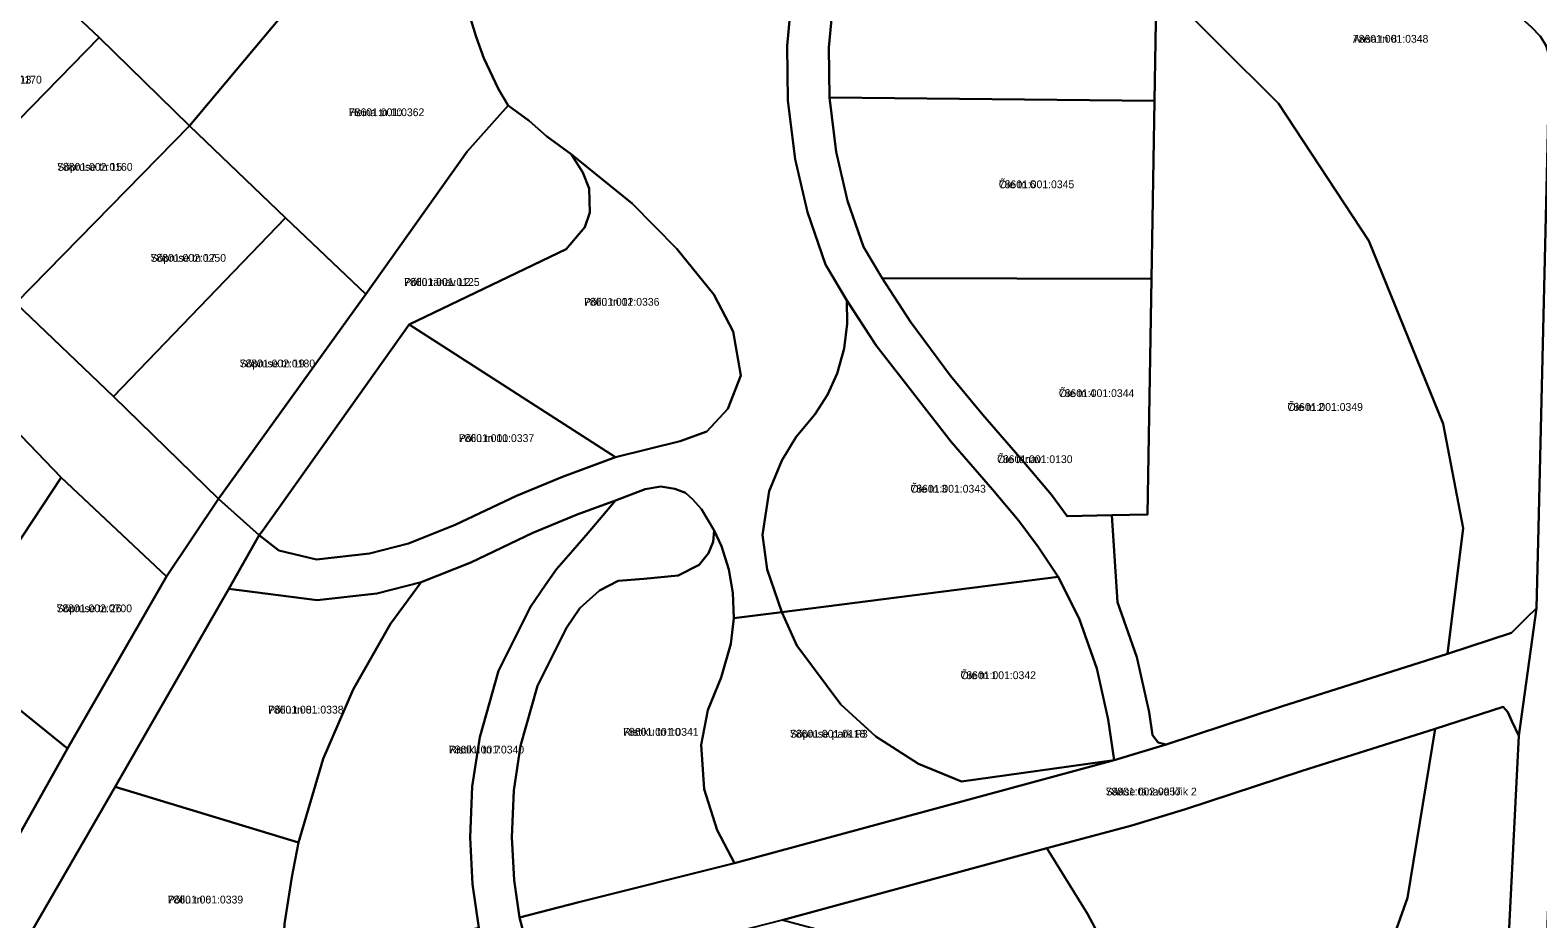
# Model space of a CAD drawing. Extents: x 587616 to 632239, y 6547421 to 6574977.
# Drawn here: x 621332.9 to 621622.8, y 6559852.1 to 6560022.9 of the extents above; entities that cross this region are included whole.
import ezdxf

# ---------------------------------------------------------------- set-up
doc = ezdxf.new("R2010")
doc.units = 0
for name, color, linetype in [('L_AADRESS', 7, 'Continuous'), ('PIIR', 7, 'Continuous'), ('TUNNUS', 7, 'Continuous')]:
    doc.layers.add(name, color=color, linetype=linetype)

msp = doc.modelspace()

# ---------------------------------------------------------------- linework, layer by layer
at = {"layer": 'PIIR'}
for points in [[(621172.9, 6560123.58), (621198.99, 6560110.14), (621218.43, 6560085.97), (621246.55, 6560050.95), (621258.82, 6560038.95), (621276.47, 6560022.13), (621295.15, 6560004.21), (621312.68, 6559987.24), (621330.19, 6559970.43), (621348.95, 6559952.47), (621369.13, 6559932.82), (621359.14, 6559917.91), (621338.93, 6559936.88), (621318.9, 6559957.64), (621298.13, 6559978.99), (621279.17, 6559996.39), (621259.98, 6560016.38), (621241.93, 6560035.63), (621232.97, 6560044.15), (621219.04, 6560061.46), (621203.25, 6560080.3), (621188.53, 6560098.22), (621176.13, 6560115.67)], [(621536.44, 6560099.15), (621540.2, 6560106.23), (621559.61, 6560089.04), (621633.19, 6560023.8), (621630.45, 6559908.6), (621626.31, 6559895.58), (621623.07, 6559813.27), (621623.06, 6559791.54), (621613.88, 6559788.46), (621614.76, 6559790.78), (621615.13, 6559793.22), (621615.42, 6559813.44), (621619.1, 6559887.24), (621622.52, 6559911.82), (621622.89, 6559927.25), (621625.01, 6560016.97), (621624.82, 6560018.4), (621624.34, 6560019.9), (621623.31, 6560021.7), (621621.48, 6560023.54), (621559.14, 6560078.76)], [(621550.22, 6560080.41), (621554.62, 6560079.78), (621556.99, 6560079.25), (621559.14, 6560078.76), (621621.48, 6560023.54), (621623.31, 6560021.7), (621624.34, 6560019.9), (621624.82, 6560018.4), (621625.01, 6560016.97), (621622.89, 6559927.25), (621622.52, 6559911.82), (621620.61, 6559909.96), (621617.69, 6559907.06), (621605.37, 6559902.99), (621608.41, 6559927.16), (621604.55, 6559947.22), (621590.3, 6559982.41), (621572.92, 6560008.78), (621549.43, 6560032.17), (621549.52, 6560037.6)], [(621363.58, 6560004.5), (621346.22, 6560021.46), (621335.3, 6560031.84), (621367.17, 6560067.51), (621388.54, 6560064.01), (621391.19, 6560062.51), (621394.58, 6560059.76), (621396.67, 6560057.03), (621397.89, 6560053.95), (621398.24, 6560050.2), (621398.45, 6560046.35), (621397.05, 6560044.66), (621391.8, 6560038.3)], [(621486.6, 6560009.93), (621486.49, 6560019.59), (621487.35, 6560029.14), (621489.03, 6560037.61), (621491.36, 6560045.61), (621493.83, 6560052.43), (621549.52, 6560037.6), (621549.43, 6560032.17), (621549.06, 6560009.34)], [(621295.15, 6560004.21), (621328.79, 6560038.03), (621335.3, 6560031.84), (621346.22, 6560021.46), (621312.68, 6559987.24)], [(621391.8, 6560038.3), (621416.5, 6560030.15), (621417.65, 6560024.98), (621418.65, 6560021.64), (621420.16, 6560017.54), (621422.98, 6560011.59), (621424.85, 6560008.43), (621416.95, 6559999.58), (621397.47, 6559972.15), (621382, 6559986.81), (621363.58, 6560004.5)], [(621548.5, 6559975.1), (621549.06, 6560009.34), (621549.43, 6560032.17), (621572.92, 6560008.78), (621590.3, 6559982.41), (621604.55, 6559947.22), (621608.41, 6559927.16), (621605.37, 6559902.99), (621573.48, 6559892.9), (621551.32, 6559885.6), (621549.78, 6559885.98), (621548.69, 6559887.36), (621548.02, 6559891.83), (621545.71, 6559902.38), (621541.97, 6559912.96), (621540.87, 6559929.64), (621547.76, 6559929.77)], [(621312.68, 6559987.24), (621346.22, 6560021.46), (621363.58, 6560004.5), (621330.19, 6559970.43)], [(621376.95, 6559925.81), (621369.13, 6559932.82), (621397.47, 6559972.15), (621416.95, 6559999.58), (621424.85, 6560008.43), (621428.89, 6560005.5), (621432.18, 6560002.51), (621436.96, 6559999.07), (621439.21, 6559995.57), (621440.38, 6559992.46), (621440.54, 6559987.87), (621439.58, 6559985.03), (621436.01, 6559980.82), (621405.8, 6559966.31), (621377.69, 6559926.74)], [(621496.71, 6559975.25), (621493.14, 6559981.26), (621490.06, 6559990.12), (621487.89, 6559999.52), (621486.6, 6560009.93), (621549.06, 6560009.34), (621548.5, 6559975.1)], [(621330.19, 6559970.43), (621363.58, 6560004.5), (621382, 6559986.81), (621348.95, 6559952.47)], [(621405.8, 6559966.31), (621436.01, 6559980.82), (621439.58, 6559985.03), (621440.54, 6559987.87), (621440.38, 6559992.46), (621439.21, 6559995.57), (621436.96, 6559999.07), (621448.64, 6559989.58), (621457.24, 6559980.88), (621464.34, 6559972.1), (621468.11, 6559964.97), (621469.57, 6559956.49), (621467.05, 6559950.12), (621463.04, 6559945.75), (621457.9, 6559943.9), (621445.48, 6559940.79)], [(621348.95, 6559952.47), (621382, 6559986.81), (621397.47, 6559972.15), (621369.13, 6559932.82)], [(621532.32, 6559929.49), (621529.27, 6559933.56), (621526.14, 6559937.3), (621524.01, 6559939.81), (621516.1, 6559948.93), (621509.88, 6559956.44), (621502.16, 6559966.83), (621496.71, 6559975.25), (621548.5, 6559975.1), (621547.76, 6559929.77), (621540.87, 6559929.64)], [(621477.43, 6559911.01), (621474.64, 6559919.25), (621473.75, 6559925.86), (621475, 6559934.26), (621477.45, 6559940.21), (621480.17, 6559944.75), (621483.75, 6559949.05), (621486.22, 6559952.83), (621488.07, 6559956.93), (621489.42, 6559961.68), (621490.02, 6559966.47), (621489.91, 6559971.03), (621495.59, 6559962.26), (621509.99, 6559943.76), (621517.93, 6559934.61), (621523.01, 6559928.58), (621526.73, 6559923.61), (621530.58, 6559917.83)], [(621387.96, 6559921.15), (621380.75, 6559922.87), (621376.95, 6559925.81), (621377.69, 6559926.74), (621405.8, 6559966.31), (621445.48, 6559940.79), (621435.27, 6559937.07), (621426.43, 6559933.41), (621414.63, 6559927.83), (621405.68, 6559924.21), (621398.19, 6559922.33)], [(621318.9, 6559957.64), (621338.93, 6559936.88), (621316.89, 6559903.64), (621295.47, 6559922.2)], [(621318.19, 6559902.52), (621316.89, 6559903.64), (621338.93, 6559936.88), (621359.14, 6559917.91), (621340.1, 6559884.83)], [(621259.58, 6559758.94), (621287.55, 6559800.32), (621311.92, 6559839.64), (621319.72, 6559848.57), (621340.1, 6559884.83), (621359.14, 6559917.91), (621369.13, 6559932.82), (621376.95, 6559925.81), (621371.15, 6559915.5), (621349.26, 6559877.47), (621329.06, 6559842.38), (621319.31, 6559827.3), (621309.9, 6559812.66), (621296.45, 6559791.82), (621270.07, 6559749.48)], [(621381.35, 6559840.54), (621381.82, 6559851.12), (621383.22, 6559860.07), (621384.54, 6559866.75), (621389.24, 6559882.8), (621395.01, 6559896.15), (621402.23, 6559908.78), (621408.11, 6559916.77), (621417.64, 6559920.59), (621429.59, 6559926.28), (621438.1, 6559929.8), (621445.45, 6559932.48), (621442.3, 6559928.77), (621440.23, 6559926.29), (621437.26, 6559922.88), (621434.11, 6559919.3), (621431.98, 6559916.3), (621429.12, 6559912.07), (621422.96, 6559899.75), (621419.38, 6559887.02), (621417.92, 6559877.53), (621417.51, 6559867.72), (621418, 6559858.73), (621419.21, 6559850.34)], [(621438.4, 6559855.27), (621427.01, 6559852.33), (621425.97, 6559859.52), (621425.52, 6559867.77), (621425.9, 6559876.75), (621427.21, 6559885.33), (621430.45, 6559896.85), (621436.04, 6559908.02), (621438.61, 6559911.81), (621442.39, 6559915.16), (621445.99, 6559917.02), (621450.92, 6559917.46), (621457.5, 6559918.07), (621461.52, 6559920.1), (621463.36, 6559922.39), (621464.25, 6559924.53), (621464.46, 6559926.7), (621465.81, 6559923.71), (621467.23, 6559919.24), (621468.01, 6559914.77), (621468.18, 6559909.84), (621467.64, 6559904.93), (621465.76, 6559898.44), (621463.19, 6559892.17), (621461.92, 6559885.5), (621462.5, 6559877.03), (621465, 6559869.09), (621468.35, 6559862.79)], [(621477.43, 6559911.01), (621530.58, 6559917.83), (621534.6, 6559909.82), (621538, 6559900.18), (621540.15, 6559890.38), (621541.32, 6559882.59), (621511.98, 6559878.47), (621503.74, 6559881.86), (621495.5, 6559887.1), (621488.75, 6559893.27), (621480.35, 6559904.63)], [(621371.15, 6559915.5), (621388.1, 6559913.32), (621399.59, 6559914.64), (621408.11, 6559916.77), (621402.23, 6559908.78), (621395.01, 6559896.15), (621389.24, 6559882.8), (621384.54, 6559866.75), (621349.26, 6559877.47)], [(621430.34, 6559839.77), (621427.01, 6559852.33), (621438.4, 6559855.27), (621468.35, 6559862.79), (621541.32, 6559882.59), (621551.32, 6559885.6), (621573.48, 6559892.9), (621605.37, 6559902.99), (621617.69, 6559907.06), (621620.61, 6559909.96), (621622.52, 6559911.82), (621619.1, 6559887.24), (621617.76, 6559890.09), (621616.98, 6559891.77), (621616.1, 6559892.85), (621603.02, 6559888.57), (621577.47, 6559880.52), (621555.06, 6559873.15), (621544.71, 6559870.04), (621528.41, 6559865.64), (621477.5, 6559851.81), (621441.61, 6559842.67)], [(621468.18, 6559909.84), (621477.43, 6559911.01), (621480.35, 6559904.63), (621488.75, 6559893.27), (621495.5, 6559887.1), (621503.74, 6559881.86), (621511.98, 6559878.47), (621541.32, 6559882.59), (621468.35, 6559862.79), (621465, 6559869.09), (621462.5, 6559877.03), (621461.92, 6559885.5), (621463.19, 6559892.17), (621465.76, 6559898.44), (621467.64, 6559904.93)], [(621296.83, 6559866.64), (621307.39, 6559882.46), (621318.19, 6559902.52), (621340.1, 6559884.83), (621319.72, 6559848.57)], [(621544.36, 6559764.54), (621570.85, 6559796.43), (621585.02, 6559820.33), (621597.74, 6559856.12), (621603.02, 6559888.57), (621616.1, 6559892.85), (621616.98, 6559891.77), (621617.76, 6559890.09), (621619.1, 6559887.24), (621615.42, 6559813.44), (621615.13, 6559793.22), (621614.76, 6559790.78), (621613.88, 6559788.46)], [(621349.26, 6559877.47), (621384.54, 6559866.75), (621383.22, 6559860.07), (621381.82, 6559851.12), (621381.35, 6559840.54), (621350.01, 6559832.57), (621342.62, 6559833.94), (621329.06, 6559842.38)], [(621528.41, 6559865.64), (621536.2, 6559853.02), (621540.02, 6559845.86), (621542.86, 6559838.25), (621544.67, 6559830.33), (621543.64, 6559806.13), (621541.25, 6559798.65), (621535.67, 6559791.41), (621531.8, 6559800.95), (621526.95, 6559810.19), (621518.75, 6559826.61), (621510, 6559837.08), (621503.05, 6559842.72), (621488.75, 6559848.79), (621477.5, 6559851.81)]]:
    msp.add_lwpolyline(points, close=True, dxfattribs=at)
for points in [[(621479.42, 6560030.27), (621478.49, 6560019.91), (621478.6, 6560009.39), (621480.01, 6559998.1), (621482.36, 6559987.89), (621485.84, 6559977.84), (621489.91, 6559971.03), (621490.02, 6559966.47), (621489.42, 6559961.68), (621488.07, 6559956.93), (621486.22, 6559952.83), (621483.75, 6559949.05), (621480.17, 6559944.75), (621477.45, 6559940.21), (621475, 6559934.26), (621473.75, 6559925.86), (621474.64, 6559919.25), (621477.43, 6559911.01), (621468.18, 6559909.84), (621468.01, 6559914.77), (621467.23, 6559919.24), (621465.81, 6559923.71), (621464.46, 6559926.7), (621461.99, 6559930.8), (621460.27, 6559932.73), (621458.92, 6559933.94), (621456.89, 6559934.75), (621454.15, 6559935.18), (621451.17, 6559934.67), (621445.45, 6559932.48), (621438.1, 6559929.8), (621429.59, 6559926.28), (621417.64, 6559920.59), (621408.11, 6559916.77), (621399.59, 6559914.64), (621388.1, 6559913.32), (621371.15, 6559915.5), (621376.95, 6559925.81), (621380.75, 6559922.87), (621387.96, 6559921.15), (621398.19, 6559922.33), (621405.68, 6559924.21), (621414.63, 6559927.83), (621426.43, 6559933.41), (621435.27, 6559937.07), (621445.48, 6559940.79), (621457.9, 6559943.9), (621463.04, 6559945.75), (621467.05, 6559950.12), (621469.57, 6559956.49), (621468.11, 6559964.97), (621464.34, 6559972.1), (621457.24, 6559980.88), (621448.64, 6559989.58), (621436.96, 6559999.07), (621432.18, 6560002.51), (621428.89, 6560005.5), (621424.85, 6560008.43), (621422.98, 6560011.59), (621420.16, 6560017.54), (621418.65, 6560021.64), (621417.65, 6560024.98)], [(621487.35, 6560029.14), (621486.49, 6560019.59), (621486.6, 6560009.93), (621487.89, 6559999.52), (621490.06, 6559990.12), (621493.14, 6559981.26), (621496.71, 6559975.25), (621502.16, 6559966.83), (621509.88, 6559956.44), (621516.1, 6559948.93), (621524.01, 6559939.81), (621526.14, 6559937.3), (621529.27, 6559933.56), (621532.32, 6559929.49), (621540.87, 6559929.64), (621541.97, 6559912.96), (621545.71, 6559902.38), (621548.02, 6559891.83), (621548.69, 6559887.36), (621549.78, 6559885.98), (621551.32, 6559885.6), (621541.32, 6559882.59), (621540.15, 6559890.38), (621538, 6559900.18), (621534.6, 6559909.82), (621530.58, 6559917.83), (621526.73, 6559923.61), (621523.01, 6559928.58), (621517.93, 6559934.61), (621509.99, 6559943.76), (621495.59, 6559962.26), (621489.9, 6559971.01), (621485.84, 6559977.84), (621482.36, 6559987.89), (621480.01, 6559998.1), (621478.6, 6560009.39), (621478.49, 6560019.91), (621479.42, 6560030.27)], [(621419.21, 6559850.34), (621418, 6559858.73), (621417.51, 6559867.72), (621417.92, 6559877.53), (621419.38, 6559887.02), (621422.96, 6559899.75), (621429.12, 6559912.07), (621431.98, 6559916.3), (621434.11, 6559919.3), (621437.26, 6559922.88), (621440.23, 6559926.29), (621442.3, 6559928.77), (621445.45, 6559932.48), (621451.17, 6559934.67), (621454.15, 6559935.18), (621456.89, 6559934.75), (621458.92, 6559933.94), (621460.27, 6559932.73), (621461.99, 6559930.8), (621464.46, 6559926.7), (621464.25, 6559924.53), (621463.36, 6559922.39), (621461.52, 6559920.1), (621457.5, 6559918.07), (621450.92, 6559917.46), (621445.99, 6559917.02), (621442.39, 6559915.16), (621438.61, 6559911.81), (621436.04, 6559908.02), (621430.45, 6559896.85), (621427.21, 6559885.33), (621425.9, 6559876.75), (621425.52, 6559867.77), (621425.97, 6559859.52), (621427.01, 6559852.33), (621430.34, 6559839.77)], [(621540.02, 6559845.86), (621536.2, 6559853.02), (621528.41, 6559865.64), (621544.71, 6559870.04), (621555.06, 6559873.15), (621577.47, 6559880.52), (621603.02, 6559888.57), (621597.74, 6559856.12), (621585.02, 6559820.33)]]:
    msp.add_lwpolyline(points, dxfattribs=at)

# ---------------------------------------------------------------- texts
at = {"layer": 'L_AADRESS'}
for s, p in [('Aasa tn 8', (621587.22, 6560020.49)), ('Sõpruse tn 13', (621320.68, 6560012.64)), ('Heina tn 10', (621394.21, 6560006.37)), ('Sõpruse tn 15', (621338.13, 6559995.87)), ('Õie tn 6', (621519.15, 6559992.52)), ('Sõpruse tn 17', (621356.09, 6559978.38)), ('Põllu tänav L2', (621404.84, 6559973.74)), ('Põllu tn 12', (621439.41, 6559969.93)), ('Sõpruse tn 19', (621373.21, 6559958.08)), ('Õie tn 4', (621530.69, 6559952.37)), ('Õie tn 2', (621574.64, 6559949.72)), ('Põllu tn 10', (621415.33, 6559943.73)), ('Õie tänav', (621518.82, 6559939.68)), ('Õie tn 3', (621502.16, 6559934)), ('Sõpruse tn 26', (621338.02, 6559911.01)), ('Õie tn 1', (621511.79, 6559898.15)), ('Põllu tn 8', (621378.68, 6559891.53)), ('Ristiku tn 10', (621446.94, 6559887.26)), ('Sõpruse park P3', (621479, 6559886.9)), ('Ristiku tn 7', (621413.4, 6559883.86)), ('Sääse tänava lõik 2', (621539.69, 6559875.79)), ('Põllu tn 6', (621359.38, 6559855.02))]:
    msp.add_text(s, height=1.5, dxfattribs=at).set_placement(p)
at = {"layer": 'TUNNUS'}
for s, p in [('78601:001:0348', (621587.22, 6560020.49)), ('78801:002:0170', (621320.68, 6560012.64)), ('78601:001:0362', (621394.21, 6560006.37)), ('78801:002:0160', (621338.13, 6559995.87)), ('78601:001:0345', (621519.15, 6559992.52)), ('78801:002:0250', (621356.09, 6559978.38)), ('78601:001:0125', (621404.84, 6559973.74)), ('78601:001:0336', (621439.41, 6559969.93)), ('78801:002:0180', (621373.21, 6559958.08)), ('78601:001:0344', (621530.69, 6559952.37)), ('78601:001:0349', (621574.64, 6559949.72)), ('78601:001:0337', (621415.33, 6559943.73)), ('78601:001:0130', (621518.82, 6559939.68)), ('78601:001:0343', (621502.16, 6559934)), ('78801:002:0700', (621338.02, 6559911.01)), ('78601:001:0342', (621511.79, 6559898.15)), ('78601:001:0338', (621378.68, 6559891.53)), ('78601:001:0341', (621446.94, 6559887.26)), ('78601:001:0118', (621479, 6559886.9)), ('78601:001:0340', (621413.4, 6559883.86)), ('78801:002:0057', (621539.69, 6559875.79)), ('78601:001:0339', (621359.38, 6559855.02))]:
    msp.add_text(s, height=1.5, dxfattribs=at).set_placement(p)

doc.saveas('drawing.dxf')
